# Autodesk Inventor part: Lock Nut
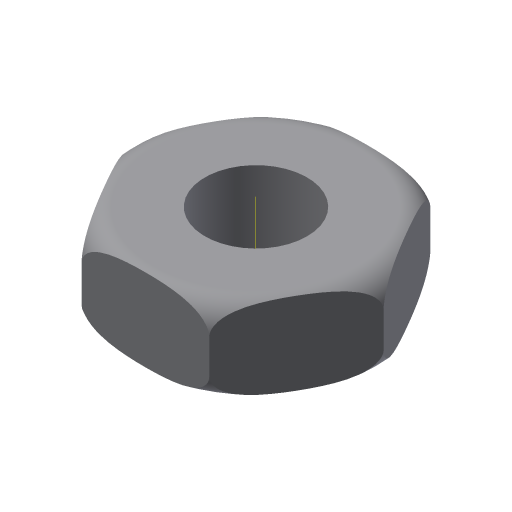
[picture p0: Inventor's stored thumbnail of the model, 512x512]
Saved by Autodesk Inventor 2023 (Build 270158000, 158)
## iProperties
Created: 2009-04
Part Number: Lock Nut
Document SubType Name: Modeling
Designer: Sham
Density: 1 g/cm^3
Material: Generic
Appearance: Default
Mass: 4.65064 g
Surface Area: 21.3319 cm^2
Volume: 4.65064 cm^3
Author: Sham
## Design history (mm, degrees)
sketch "Sketch1"
  geometry: L1 (7.5, 12.99)-(15, 0); L2 (15, 0)-(7.5, -12.99); L3 (7.5, -12.99)-(-7.5, -12.99); L4 (-7.5, -12.99)-(-15, 0); L5 (-15, 0)-(-7.5, 12.99); L6 (-7.5, 12.99)-(7.5, 12.99); C1 r 6 at (0, 0); 1 further point
  constraints: 12 end point, 1 centre point, 1 coincident, 13 other
  dimensions: "d0" = 30 distance of L1.end L4.end; "d1" = 12 diameter of C1
extrude "Extrusion1" new body sketch "Sketch1" distance "d2" = 10; taper "d3" = 0 deg
sketch "Sketch2"
  geometry: L1 (-12, 0)-(-12, -0.022); L2 (-15, 7)-(-15, 3); L3 (0, -2.87)-(0, 12.87) reference; A1 r 3 centre (-12, 7) between (-12, 10) and (-15, 7); A2 r 3 centre (-12, 3) between (-15, 3) and (-12, 0)
  constraints: 4 end point, 4 point on circle, 2 centre point, 1 tangent
revolve "Revolution1" sketch "Sketch2" stored, may be unused: angle "d7" = 90 deg
body "Solid1"
other parameters: "d6" = 90 deg
